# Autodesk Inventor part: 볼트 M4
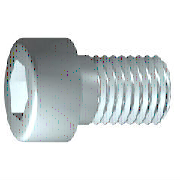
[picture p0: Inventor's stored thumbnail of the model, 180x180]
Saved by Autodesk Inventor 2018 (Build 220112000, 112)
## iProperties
IsCustomPart: 1
Created: 2012-02
Part Number: 볼트 M4
Material: 강철, 연강
Description: 6각머리 태핑 나사
Document SubType Name: Modeling
Standard: KS B 1003
Designer: mduedu
Standards Organization: KS
Language: ko-KR
Size Designation: M 4 x 10
Categories: <MemberInstance><Categories><Category DisplayName="조임쇠" InternalName="e4da775c-781d-43d5-af7c-5136215cf5a6" Mnemonic="FSTN"><Category DisplayName="볼트" InternalN
Density: 7.86 g/cm^3
Mass: 2.0371 g
Surface Area: 3.0572 cm^2
Volume: 0.259174 cm^3
Appearance: 강철
Author: mduedu
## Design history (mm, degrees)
sketch "스케치1"
  geometry: L1 (-1, 0)-(10, 0); L2 (10, 0)-(10, 2); L3 (10, 2)-(1.75, 2); L4 (1.75, 2)-(1.32, 2); L5 (1.32, 2)-(0, 2); L6 (0, 2)-(0, 3.5); L7 (0, 3.5)-(-4, 3.5); L8 (-4, 3.5)-(-4, 1.732); L9 (-4, 1.732)-(-2, 1.732); L10 (-2, 1.732)-(-1, 0); L11 (-6.8, 0)-(12.8, 0) reference; L12 (0, -0.7)-(0, 4.2) reference; L13 (1.75, 2)-(0, 2)
  constraints: 22 end point, 6 parallel, 2 collinear, 2 perpendicular, 1 horizontal, 1 point on line
  dimensions: "d1" = 8.25 distance from line of L3.end L2 (= GEL); "d2" = 0.42952 distance of L4.end L3.end (computed from GAL); "d3" = 4 distance between parallel lines of L8 L6 (= KOH); "d4" = 2 distance of L8.end L9.end (= INTI); "d5" = 60 deg angle of L10 L1; "d6" = 4 diameter of L3 L1 (= GD); "d7" = 4 diameter of L5 L1 (= BDM); "d8" = 3.4641 diameter of L9 L1 (= 1.1547 x SW); "d9" = 7 diameter of L7 L1 (= KOD); "d26" = 10 distance between parallel lines of L12 L2 (= NLG)
revolve "본체" sketch "스케치1" stored, may be unused: angle "d10" = 90 deg
sketch "스케치2"
  geometry: L1 (0, -4.9)-(0, 4.9) reference; L2 (-4.9, 0)-(4.9, 0) reference; L3 (1.732, 0)-(0.866, -1.5); L4 (0.866, -1.5)-(-0.866, -1.5); L5 (-0.866, -1.5)-(-1.732, 0); L6 (-1.732, 0)-(-0.866, 1.5); L7 (-0.866, 1.5)-(0.866, 1.5); L8 (0.866, 1.5)-(1.732, 0); 2 further points
  constraints: 12 end point, 1 coincident, 1 horizontal alignment, 1 point on line, 12 other
extrude "슬롯" join sketch "스케치2" stored distance "d11" = 10; taper "d12" = 0 deg
workplane "Work Plane1"
fillet "Fillet2" dims "d30" = 0.1 (= R)
body "Solid1"
fillet "모깎기1" dims "d17" = 0.4 (= RR)
feature "스레드" dims "d13" = 8.25 (= GEL), "d14" = 0
chamfer "모따기1" distance "d15" = 0.42941 (= -0.5 x SPD + 0.5 x GD); stored, may be unused: second distance "d16" = 0.42941 (= GUL), angle "d27" = 45 deg
other parameters: "GD" = 4 (= NND) [user parameter; used in 2 equation terms], "NLG" = 10 [user parameter; used in 1 equation term], "GEL" = 8.25 [user parameter; used in 2 equation terms], "KOD" = 7 [user parameter; used in 1 equation term], "KOH" = 4 [user parameter; used in 1 equation term], "INTI" = 2 [user parameter; used in 1 equation term], "GAL" = 0.42941 (= 0.61345 x PTC) [user parameter; used in 1 equation term], "GUL" = 0.42941 (= 0.61345 x PTC) [user parameter; used in 1 equation term], "BDM" = 4 (= NND) [user parameter; used in 1 equation term], "SW" = 3 [user parameter; used in 2 equation terms], "RR" = 0.4 [user parameter; used in 1 equation term], "SPD" = 3.14117 (= NND - 1.2269 x PTC) [user parameter; used in 1 equation term], "d19" = 0, "d28" = 0, "d29" = 0, "R" = 0.1 [user parameter; used in 1 equation term], "PHH" = 0.2 [user parameter], "GD1" = 3.14117 (= THREADDIA - 1.2269 x PTC) [user parameter], "THREADDIA" = 4 [user parameter; used in 1 equation term], "FAWI" = 45 deg [user parameter], "TPU" = 14.28571 (computed from PTC) [user parameter], "PTC" = 0.7 [user parameter; used in 5 equation terms], "NND" = 4 [user parameter; used in 3 equation terms], "TOA" = 30 deg [user parameter], "E0" = 3.465 (= 1.155 x SW) [user parameter]
